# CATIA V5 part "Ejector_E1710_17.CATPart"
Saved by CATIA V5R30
Part number: Vyhazovac_4x160_4
Nomenclature: E1710/4x160
Description: MEUSBURGER
Property "Material": "1.221"
Publications: "__DrillHole", "Base"
Bounding box of the stored display mesh (mm): x -3.996 to 3.996, y -3.999 to 3.999, z 0 to 152
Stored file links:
  E:\Bakalarka\Model\Forma_v7\Ejector_E1710_17.CATPart
  E:\dev\MoldDesign\intel_a\startup\components\MoldCatalog\Ejector\Meusburger\Ejector_E1710\TableE1710.txt
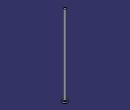
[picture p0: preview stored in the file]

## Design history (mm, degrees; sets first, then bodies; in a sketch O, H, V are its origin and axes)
Parameters
  Ref = "E1710/4x160" {design table}
  D1 = 4 mm {design table}
  D3 = 8 mm {design table}
  L = 160 mm {design table}
  L3 = 3 mm {design table}
  R = 0.3 mm {design table}
  k_d3 = 9 mm {design table}
  k_d1 = 4.2 mm {design table}
  k_F = 0.3 mm {design table}
  kl = 17 mm {design table}
  Mat = "1.221" {design table}
  HeatTreat = "ISO6751" {design table}
  Offset_Parting = 10 mm
  Anti_Rotation = "Normal"
  Anti_Rotation_D = 2.3 mm
  Anti_Rotation_D_Icut = 2.3 mm
  Add_Length_L = 0.8377 mm
  Add_Length_D3 = 0 mm
  SupplierRef = "Meusburger 2017"
  BmpRef = "F_MldEjectorD1"
  DrillHole_Length = 225 mm
  ValidationTest = false
  Anti_Rotation_D_min = 2.3 mm {= OffSet_D1 /2}
  Anti_Rotation_D_max = 3.925 mm {= D3/2-0.075mm}
  Anti_Rotation_D_ref = 2.3 mm {= Anti_Rotation_D}
  Anti_Rotation_D_Icut_ref = 2.3 mm {= Anti_Rotation_D_Icut}
  Anti_Rotation_Ref_Icut = 2.3246 mm
  Offset_L = 20 mm
  D = 4 mm {= D1}
  OffSet_D1 = 4.6 mm {= D1+2*R}
  OffSet_D3 = 9 mm {= D3+1mm}
  XG_Split = 25.5 mm
  YG_Split = 22.5 mm
  ZG_Split = -198 mm
  DirX_Split = 0 mm
  DirY_Split = 0 mm
  DirZ_Split = 1 mm
Set1 "BaseBody"
  Point1 "Base": (0, 0, 0)
  Plane1: type Offset, RefPlane xy-plane, Offset 225 {= DrillHole_Length}, reversed
  Sketch1 "Sketch.2" on xy-plane, origin (0, 0, 0), H (1, 0, 0), V (0, 1, 0)
    point P1 (-0.46, 1.1623)
    point P2 (0.46, 1.1623)
    construction line L1 (-0.46, 1.1623) -> (0.46, 1.1623)
    point P3 (0.46, -1.1623)
    line L2 (0.46, -1.1623) -> (0.46, 1.1623)
    point P4 (-0.46, -1.1623)
    construction line L3 (0.46, -1.1623) -> (-0.46, -1.1623)
    line L4 (-0.46, 1.1623) -> (-0.46, -1.1623)
    point P5 (-0.21, 1.1623)
    arc A1 centre (-0.21, 1.1623) radius 0.25 from (-0.21, 1.4123) to (-0.46, 1.1623) ccw
    point P7 (0.21, 1.1623)
    point P8 (0.21, 1.4123)
    arc A2 centre (0.21, 1.1623) radius 0.25 from (0.46, 1.1623) to (0.21, 1.4123) ccw
    line L5 (-0.21, 1.4123) -> (0.21, 1.4123)
    point P9 (-0.46, -1.1623)
    arc A3 centre (-0.21, -1.1623) radius 0.25 from (-0.46, -1.1623) to (-0.21, -1.4123) ccw
    point P11 (0.21, -1.4123)
    line L6 (-0.21, -1.4123) -> (0.21, -1.4123)
    point P12 (0.46, -1.1623)
    arc A4 centre (0.21, -1.1623) radius 0.25 from (0.21, -1.4123) to (0.46, -1.1623) ccw
    point P14 (-0.46, 1.1623)
    point P15 (-0.46, -1.1623)
    point P16 (0.46, 1.1623)
    point P17 (0.46, -1.1623)
    reference projected circle E1 centre (0, 0) radius 1.25 from edge [face of Shaft1 from Sketch2.L3 | face of Shaft1 from Sketch2.L4]
    reference projected circle E2 centre (0, 0) radius 1.25 from edge [face of Shaft1 from Sketch2.L3 | face of Shaft1 from Sketch2.L4]
    reference projected circle E3 centre (0, 0) radius 1.25 from edge [face of Shaft1 from Sketch2.L3 | face of Shaft1 from Sketch2.L4]
    reference projected circle E4 centre (0, 0) radius 1.25 from edge [face of Shaft1 from Sketch2.L3 | face of Shaft1 from Sketch2.L4]
    point P18 (-0.46, -1.1623)
    point P19 (-0.21, -1.4123)
    point P20 (0.21, -1.4123)
    point P21 (0.46, -1.1623)
    point P22 (-0.21, -1.4123)
    point P23 (0.21, -1.4123)
    distance P14 P15 = 2.3246 (reference)
    distance P16 P17 = 2.3246 (reference)
    distance L1 P14 = 0 (reference)
    radius A1 = 2
    distance L4 V = 2.31
    distance L2 V = 3.935
    distance L5 L6 = 8
    horizontal: L1 H, L3 H, L5 H
    vertical: L2 V, L4 V
    coincidence: P5 L1, P7 L1, P3 P12, P14 L4, P15 L4, P16 L2, P17 L2, P14 E1, P15 E2, P16 E3, P17 E4, P3 P21, P4 P18, P20 P23, P19 P22
    tangency: A1 L4, A2 L2, A2 L5, A1 L5
    symmetry: P1 P9 H, A1 A3 H, P8 P11 H, L5 L6 H, P2 P12 H, A2 A4 H
  DatumSurface1
Body1 "PartBody" (main body)
  Sketch2 "Sketch.1" on zx-plane, origin (0, 0, 0), H (-1, 0, 0), V (0, 0, 1)
    point P1 (0, 160)
    line L1 (2, 160) -> (0, 160)
    line L2 (2, 3) -> (2, 160)
    line L3 (4, 3) -> (2, 3)
    line L4 (4, 0) -> (4, 3)
    point P5 (0, 0)
    line L5 (0, 0) -> (4, 0)
    point P6 (0, 160)
    axis line L6 (0, 160) -> (0, 0)
    point P7 (0, 0)
    point P8 (2, 3)
    point P9 (2, 3)
    line L7 (0, 160) -> (0, 0)
    distance L5 L3 = 3 {= L3}
    distance L5 L1 = 160 {= L}
    distance L2 L6 = 2 {= D1 /2}
    distance L4 L6 = 4 {= D3 /2}
    coincidence: L6 P5, P1 L6, L5 H, L6 V, P7 O, P6 P1, P8 P9
    vertical: L2 V, L7 V
    horizontal: L1 H
  Shaft1 "Shaft.1": profile Sketch2, axis Sketch2.L6, angle 360
  Pocket1 "Pocket.1": profile Sketch1, direction (0, 0, 1), length 4, outer side, deactivated
  Pocket2 "Pocket.2": profile Sketch1, direction (0, 0, 1), length 4, outer side, deactivated
  Fillet1: radius 0.3 {= R}, on edge [face of Shaft1 from Sketch2.L2 | face of Shaft1 from Sketch2.L3]
  Pocket3: profile face of Shaft1 from Sketch2.L1, direction along face of Shaft1 from Sketch2.L1 reversed, up to face of DatumSurface1
Body2 "__DrillHole"
  Sketch3 "Sketch.3" on face of Shaft1, origin (0, 0, 0), H (1, 0, 0), V (0, -1, 0)
    point P1 (0, 0)
    reference projected point E1 (0, 0) from Point1
    coincidence: E1 P1
  Hole1 "Hole.1": placed by Sketch3, at (0, 0, 0) direction (0, 0, 1), diameter 4.6 {= OffSet_D1}, depth 140 {= L-Offset_L}
  Sketch4 "Sketch.4" on face of Shaft1, origin (0, 0, 0), H (1, 0, 0), V (0, -1, 0)
    point P1 (0, 0)
    reference projected point E1 (0, 0) from Point1
    coincidence: E1 P1
  Hole2 "Hole.2": placed by Sketch4, at (0, 0, 0) direction (0, 0, 1), diameter 4 {= D1}, depth 160 {= L}
  Sketch5 "Sketch.5" on face of Shaft1 from Sketch2.L3, origin (0, 0, 3), H (1, 0, 0), V (0, 1, 0)
    point P1 (0, 0)
    reference projected point E1 (0, 0) from Point1
    coincidence: E1 P1
  Hole3 "Hole.3": placed by Sketch5, at (0, 0, 3) direction (0, 0, -1), diameter 9 {= OffSet_D3}, depth 228 {= L3 +DrillHole_Length}
  Chamfer1: length 0.3 {= k_F}, angle 45, on edge [face of Hole1 | face of Hole3]
  Body3 "__Body.1"
    Pocket4 "Pocket.3": profile Sketch1, direction (0, 0, -1), length 225, opposite side length 3, deactivated
  Assemble1: tool Body3
  Chamfer2: length 0.3 {= k_F}, angle 45, on edge [start face of Pocket4 | face of Hole1], deactivated
  Body4 "__Body.2"
    Pocket5 "Pocket.4": profile Sketch1, direction (0, 0, -1), length 225, opposite side length 3, deactivated
  Assemble2: tool Body4
  Chamfer3: length 0.3 {= k_F}, angle 45, on edge [start face of Pocket5 | face of Hole1], deactivated
Relations
  design table "TableE1710", configuration 187, drives Ref, D1, D3, L, L3, R, k_d3, k_d1, k_F, kl, Mat, HeatTreat
  Offset_L = 20mm (deactivated)
  rule "Cut_Head_rule":
    let sketch_cut (length)
    let PartBody_Pocket_Sketch (Boolean)
    let I_PartBody_Pocket (Boolean)
    let D_PartBody_Pocket (Boolean)
    let N_DrillHole_Hole (Boolean)
    let N_DrillHole_Hole_Sketch (Boolean)
    let I_DrillHole_Pocket (Boolean)
    let D_DrillHole_Pocket (Boolean)
    /* --------------------------------------------------------------------------------------*/
    if Anti_Rotation =="Normal"
    {
    	sketch_cut=Anti_Rotation_D_max
    	PartBody_Pocket_Sketch = false
    	I_PartBody_Pocket = false
    	D_PartBody_Pocket = false
    	N_DrillHole_Hole = true
    	N_DrillHole_Hole_Sketch = true
    	I_DrillHole_Pocket = false
    	D_DrillHole_Pocket = false
    	Chamfer1.Activity= true
    	Chamfer2.Activity= false
    	Chamfer3.Activity= false
    }
    if Anti_Rotation == "I_Cut"
    {
    	sketch_cut=Anti_Rotation_D_Icut_ref
    	PartBody_Pocket_Sketch = true
    	I_PartBody_Pocket = true
    	D_PartBody_Pocket = false
    	N_DrillHole_Hole = false
    	N_DrillHole_Hole_Sketch = false
    	I_DrillHole_Pocket = true
    	D_DrillHole_Pocket = false
    	Chamfer1.Activity= false
    	Chamfer2.Activity= true
    	Chamfer3.Activity= false
    }
    if Anti_Rotation =="D_Cut"
    {
    	sketch_cut=Anti_Rotation_D_max
    	PartBody_Pocket_Sketch = true
    	I_PartBody_Pocket = false
    	D_PartBody_Pocket = true
    	N_DrillHole_Hole = false
    	N_DrillHole_Hole_Sketch = false
    	I_DrillHole_Pocket = false
    	D_DrillHole_Pocket = true
    	Chamfer1.Activity= false
    	Chamfer2.Activity= false
    	Chamfer3.Activity= true
    }
    /* --------------------------------------------------------------------------------------*/
    Sketch1.distance(L2 V) = sketch_cut+0.01mm
    Sketch1.distance(L4 V) =Anti_Rotation_D_ref+0.01mm
    Sketch1.radius(A1) =D/2
    Pocket4.FirstLimit.Depth = DrillHole_Length
    Pocket5.FirstLimit.Depth = DrillHole_Length
    Pocket1.FirstLimit.Depth = L3+1mm
    Pocket2.FirstLimit.Depth = L3+1mm
    Pocket4.SecondLimit.Depth = L3
    Pocket5.SecondLimit.Depth =L3
    Pocket1.Activity = I_PartBody_Pocket
    Pocket2.Activity = D_PartBody_Pocket
    Sketch1.Activity =PartBody_Pocket_Sketch
    Hole3.Activity= N_DrillHole_Hole
    Sketch5.Activity = N_DrillHole_Hole_Sketch
    Pocket4.Activity = I_DrillHole_Pocket
    Pocket5.Activity  = D_DrillHole_Pocket
  rule "Anti_Rotation_Icut_constrain":
    let Ref1(length)
    let Ref2(length)
    let Ref3(length)
    let Diam1(length)
    let Diam2(length)
    let Add_Length_Lmin (length)
    Ref1=Sketch1.distance(P14 P15)
    Ref2=Sketch1.distance(P16 P17)
    Diam1=D
    Diam2=D3
    /* --------------------------------------------------------------------*/
    if Ref1 >Ref2
    	Anti_Rotation_Ref_Icut = Ref1
    else
    	Anti_Rotation_Ref_Icut  =Ref2
    Add_Length_D3 .InferiorRange=Anti_Rotation_Ref_Icut /2+Diam1/2 -Diam2/2
    if Add_Length_D3 .InferiorRange<0mm
    	Add_Length_D3 .InferiorRange=0mm
    if ValidationTest == "true"
    	Ref3   = 2*Add_Length_L +Anti_Rotation_Ref_Icut  +2*Diam1/2
    else
    	Ref3  =Diam2+2*Add_Length_D3
    if Ref3 <Diam2
    {
    	Ref3 =Diam2
    }
    /* --------------------------------------------------------------------*/
    Sketch1.distance(L5 L6) = Ref3
    Add_Length_L .InferiorRange=Diam2/2-Anti_Rotation_Ref_Icut/2-Diam1/2
    Add_Length_Lmin=Diam2/2-Anti_Rotation_Ref_Icut/2-Diam1/2
    if Add_Length_Lmin<0mm
    	Add_Length_L .InferiorRange=0mm
    else
    	Add_Length_L .InferiorRange=Add_Length_Lmin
